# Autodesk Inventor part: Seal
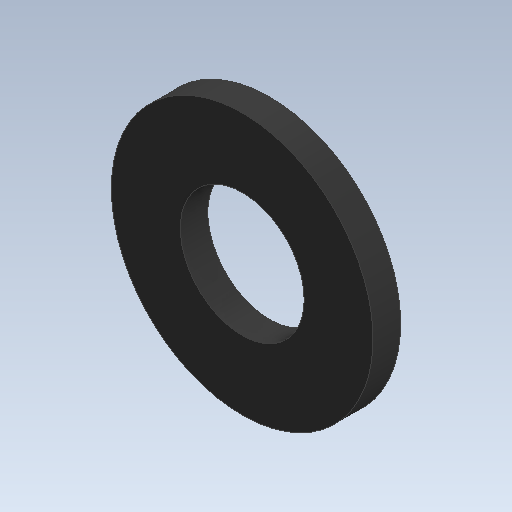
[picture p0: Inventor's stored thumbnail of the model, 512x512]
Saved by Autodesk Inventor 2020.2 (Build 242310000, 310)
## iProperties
Created: 2020-01
Part Number: Seal
Material: Rubber
Document SubType Name: Modeling
Designer: thira
Density: 0.93 g/cm^3
Appearance: Rubber - Black
Mass: 3.27228 g
Surface Area: 24.6301 cm^2
Volume: 3.51858 cm^3
Author: thira
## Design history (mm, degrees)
workplane "Work Plane1"
sketch "Sketch1"
  geometry: C1 r 9 at (0, 0) reference; C2 r 19 at (0, 0) reference; 1 further point
  node "Reference1"
workplane "Work Plane2"
extrude "Extrusion1" new body sketch "Sketch1" stored distance "d0" = 10; taper "d1" = 0 deg
body "Solid1"
